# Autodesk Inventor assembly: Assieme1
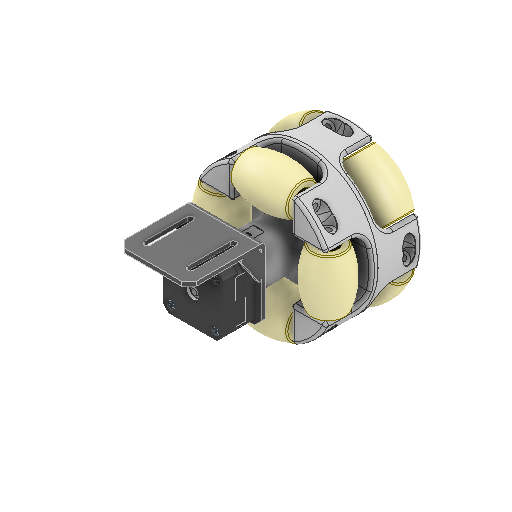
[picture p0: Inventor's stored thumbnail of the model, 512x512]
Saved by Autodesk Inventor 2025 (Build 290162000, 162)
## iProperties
Created: 2025-05
Part Number: Assieme1
Document SubType Name: Assembly
Designer: R5800u
Author: R5800u
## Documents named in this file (8)
- C:\Users\R5800u\Desktop\mecanum7\Assieme1.iam
- C:\Users\R5800u\Desktop\mecanum7\Parte1c.ipt
- C:\Users\R5800u\Desktop\mecanum7\Parte1a.ipt
- C:\Users\R5800u\Desktop\mecanum6\nema17_pancake.iam
- C:\Users\R5800u\Desktop\mecanum6\rullo.ipt
- C:\Users\R5800u\Documents\Inventor\Content Center Files\R2025\it-IT\AS 1112 (2)\AS 1112 - M4  Tipo 5.ipt
- C:\Users\R5800u\Documents\Inventor\Content Center Files\R2025\it-IT\AS 1421(2)\AS 1421 - M4 x 16 Punta a coppa.ipt
- C:\Users\R5800u\Desktop\mecanum6\NEMA 17 A-Body.ipt
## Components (14 placed, 7 different names)
1. Parte1c:1 — Coincidente:1, Coincidente:2, Angolo:1, Coincidente:6, Coincidente:7
2. Parte1a:1 — Coincidente:1, Coincidente:2, Angolo:1, Rotazionale:1, Angolo:2, Coincidente:3, Coincidente:4, Angolo:3
3. nema17_pancake:1 [sub-assembly] — Rotazionale:1, Angolo:2, Rotazionale:2, Angolo:4
4. AS 1112 (2) - Metrico M4  Tipo 5:1 — Angolo:3
5. AS 1421 Punta a coppa - Metrico M4 x 16 Punta a coppa:1
6. NEMA 17 A-Body:1 — Rotazionale:2, Angolo:4
7. rullo:1 — Coincidente:3, Coincidente:4
8. rullo:2
9. rullo:3
10. rullo:4
11. rullo:5 — Coincidente:6, Coincidente:7
12. rullo:6
13. rullo:7
14. rullo:8
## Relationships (12: Mate 6, Angle 4, RevoluteJoint 2)
- Coincidente:1 [Mate]: Parte1c:1 ↔ Parte1a:1
- Coincidente:2 [Mate]: Parte1c:1 ↔ Parte1a:1
- Angolo:1 [Angle]: Parte1c:1 ↔ Parte1a:1
- Rotazionale:1 [RevoluteJoint]: Parte1a:1 ↔ nema17_pancake:1
- Angolo:2 [Angle]: Parte1a:1 ↔ nema17_pancake:1
- Coincidente:3 [Mate]: Parte1a:1 ↔ rullo:1
- Coincidente:4 [Mate]: Parte1a:1 ↔ rullo:1
- Angolo:3 [Angle]: Parte1a:1 ↔ AS 1112 (2) - Metrico M4  Tipo 5:1
- Rotazionale:2 [RevoluteJoint]: nema17_pancake:1 ↔ NEMA 17 A-Body:1
- Angolo:4 [Angle]: nema17_pancake:1 ↔ NEMA 17 A-Body:1
- Coincidente:6 [Mate]: Parte1c:1 ↔ rullo:5
- Coincidente:7 [Mate]: Parte1c:1 ↔ rullo:5
